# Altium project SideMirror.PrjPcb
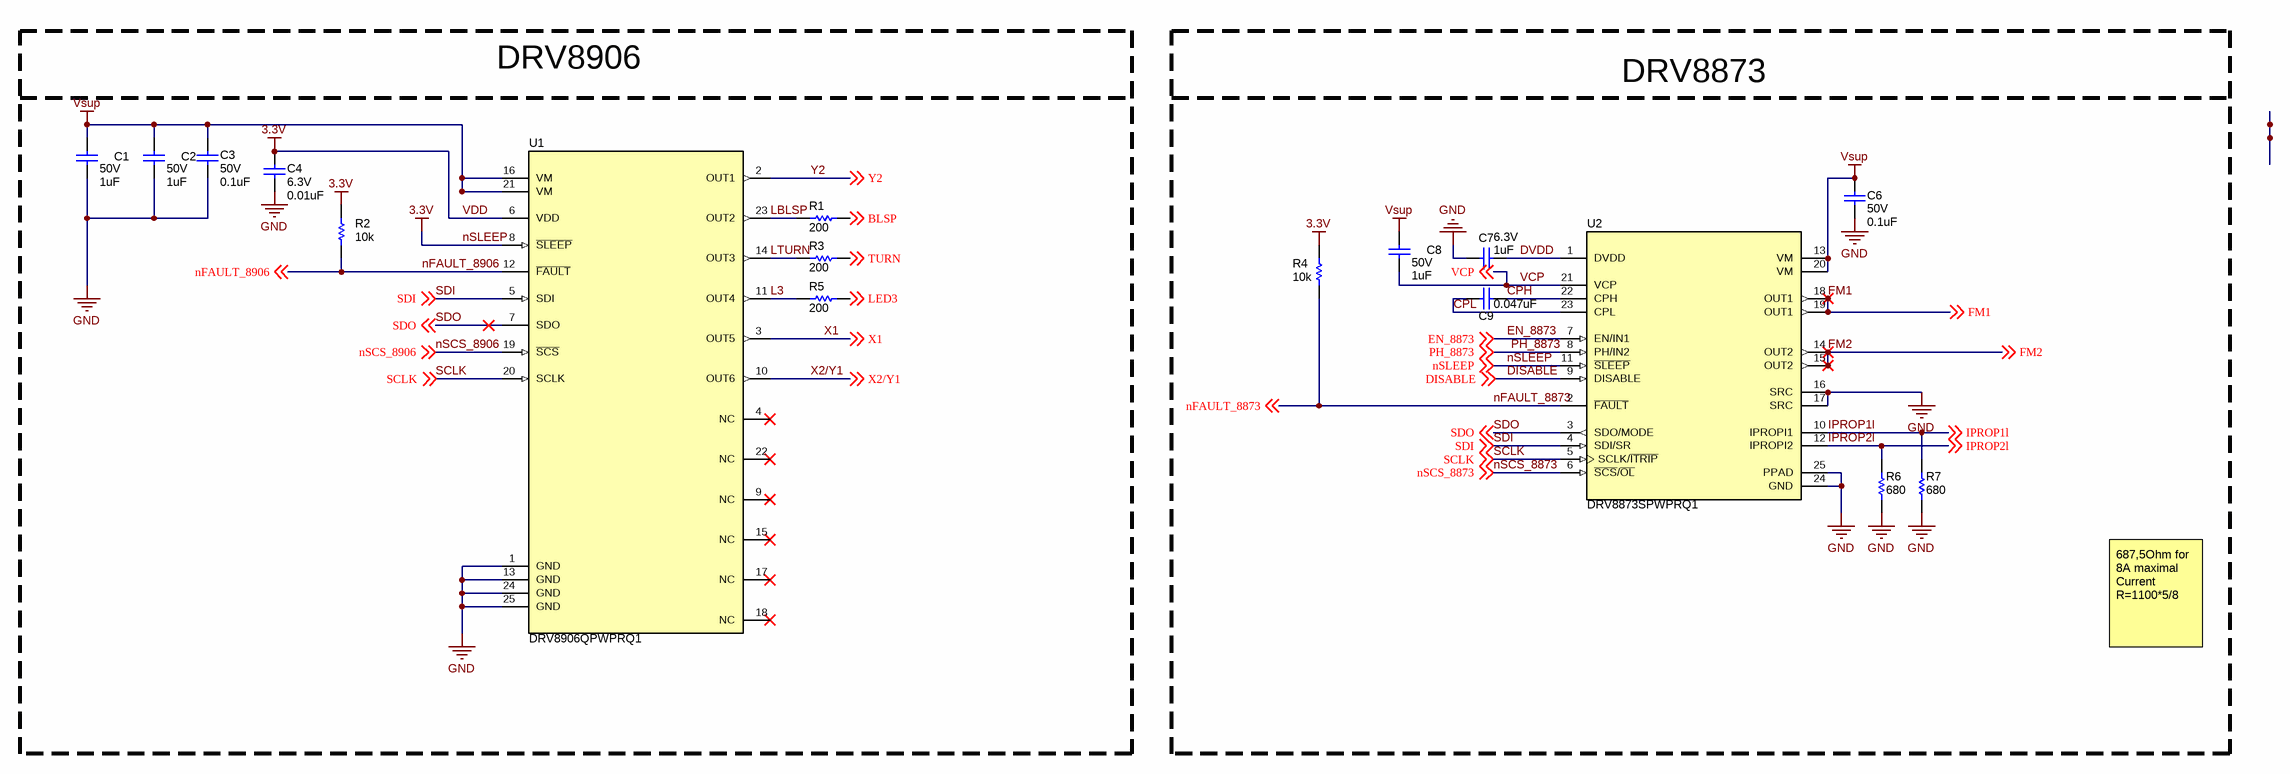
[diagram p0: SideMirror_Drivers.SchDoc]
TID: TIDA-020027; TechSupport: http://www.ti.com/support; SCH_Rev: E1; PRJ_Title: Side Mirror Module; PRJ_Number: TIDA-020027; PRJ_Engineer: Alisa Knorr; PRJ_Customer: Public Release; PCB_Rev: E1; PCB_Layout: Alisa Knorr; CopyrightYear: 2019
3 sheets, 78 parts. Net scope: global (net labels, ports and power ports of the same name join across sheets).
Board file: SideMirror_PCB.PcbDoc
Sheets:
  SideMirror_Drivers.SchDoc
  SideMirror_Logic_TLIN1028.SchDoc
  SideMirror_Hardware.SchDoc

## Sheet SideMirror_Drivers.SchDoc
size 431 x 279 mm; Date: Not shown in title block; ApprovedBy: Not shown in title block; CheckedBy: Not shown in title block; Author: Not shown in title block; CompanyName: Not shown in title block; Engineer: Not shown in title block; Organization: Not shown in title block; Address1: Not shown in title block; Address2: Not shown in title block; Address3: Not shown in title block; Address4: Not shown in title block; DocumentNumber: 2; Revision: Use project parameter SCH_Rev; SheetNumber: 1; SheetTotal: 3; PageSetup: Record=PageOptions¦CenterHorizontal=True¦CenterVertical=True¦PrintScale=1.00¦XCorrection=1.00¦YCorrection=1.00¦PrintKind=0¦BorderSize=5000000¦LeftOffset=0¦BottomOffset=0¦Orientation=2¦PaperLength=1000¦PaperWidth=1000¦Scale=100¦PaperSource=15¦PrintQuality=600¦MediaType=1¦DitherType=10¦PaperKind=Letter¦PrintScaleMode=1

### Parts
C1  VDC_V: 50V  ValueDisplayed: 1uF  [0603]  (hidden comment: UMK107AB7105KA-T)
C2  VDC_V: 50V  ValueDisplayed: 1uF  [0603]  (hidden comment: UMK107AB7105KA-T)
C3  VDC_V: 50V  ValueDisplayed: 0.1uF  [0603]  (hidden comment: C0603C104J5RACTU)
C4  VDC_V: 6.3V  ValueDisplayed: 0.01uF  [0603]  (hidden comment: GRM188R70J103KA01D)
C6  VDC_V: 50V  ValueDisplayed: 0.1uF  [0603]  (hidden comment: C0603C104J5RACTU)
C7  VDC_V: 6.3V  ValueDisplayed: 1uF  [0603]  (hidden comment: GRM185R60J105KE26D)
C8  VDC_V: 50V  ValueDisplayed: 1uF  [0603]  (hidden comment: UMK107AB7105KA-T)
C9  ValueDisplayed: 0.047uF  [0402L]  (hidden comment: Capacitor)
R1  ValueDisplayed: 200  [0603]  (hidden comment: CRCW0603200RJNEA)
R2  ValueDisplayed: 10k  [0402L]  (hidden comment: Resistor)
R3  ValueDisplayed: 200  [0603]  (hidden comment: CRCW0603200RJNEA)
R4  ValueDisplayed: 10k  [0402L]  (hidden comment: Resistor)
R5  ValueDisplayed: 200  [0603]  (hidden comment: CRCW0603200RJNEA)
R6  ValueDisplayed: 680  [0603]  (hidden comment: RC0603FR-07680RL)
R7  ValueDisplayed: 680  [0603]  (hidden comment: RC0603FR-07680RL)
U1  DRV8906QPWPRQ1  [PWP0024N_N]
U2  DRV8873SPWPRQ1  [PWP0024J_M]

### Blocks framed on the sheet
DRV8906: C1-C4 R1-R3 R5 U1
DRV8873: C6-C9 R4 R6 R7 U2

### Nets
3.3V: C4.1 R2.2 R4.2 U1.6(VDD) U1.8(~{SLEEP}) U2.11(~{SLEEP}) ; off-sheet nSLEEP  [also labelled nSLEEP, VDD]
GND: C1.2 C2.2 C3.1 C4.2 C6.1 C7.2 R6.1 R7.1 U1.1(GND) U1.13(GND) U1.24(GND) U1.25(GND) U2.16(SRC) U2.17(SRC) U2.24(GND) U2.25(PPAD)
Vsup: C1.1 C2.1 C3.2 C6.2 C8.1 U1.16(VM) U1.21(VM) U2.13(VM) U2.20(VM)
BLSP: R1.2 ; off-sheet BLSP
CPH: C9.1 U2.22(CPH)
CPL: C9.2 U2.23(CPL)
DISABLE: U2.9(DISABLE) ; off-sheet DISABLE
DVDD: C7.1 U2.1(DVDD)
EN_8873: U2.7(EN/IN1) ; off-sheet EN_8873
FM1: U2.18(OUT1) U2.19(OUT1) ; off-sheet FM1
FM2: U2.14(OUT2) U2.15(OUT2) ; off-sheet FM2
IPROP1l: R7.2 U2.10(IPROPI1) ; off-sheet IPROP1l
IPROP2l: R6.2 U2.12(IPROPI2) ; off-sheet IPROP2l
L3: R5.1 U1.11(OUT4)
LBLSP: R1.1 U1.23(OUT2)
LED3: R5.2 ; off-sheet LED3
LTURN: R3.1 U1.14(OUT3)
nFAULT_8873: R4.1 U2.2(~{FAULT}) ; off-sheet nFAULT_8873
nFAULT_8906: R2.1 U1.12(~{FAULT}) ; off-sheet nFAULT_8906
nSCS_8873: U2.6(~{SCS}/~{OL}) ; off-sheet nSCS_8873
nSCS_8906: U1.19(~{SCS}) ; off-sheet nSCS_8906
PH_8873: U2.8(PH/IN2) ; off-sheet PH_8873
SCLK: U1.20(SCLK) U2.5(SCLK/~{ITRIP}) ; off-sheet SCLK
SDI: U1.5(SDI) U2.4(SDI/SR) ; off-sheet SDI
SDO: U1.7(SDO) U2.3(SDO/MODE) ; off-sheet SDO
TURN: R3.2 ; off-sheet TURN
VCP: C8.2 U2.21(VCP) ; off-sheet VCP
X1: U1.3(OUT5) ; off-sheet X1
X2/Y1: U1.10(OUT6) ; off-sheet X2/Y1
Y2: U1.2(OUT1) ; off-sheet Y2

Not connected (* = marked no-connect by the designer): U1 4(NC)* 9(NC)* 15(NC)* 17(NC)* 18(NC)* 22(NC)*

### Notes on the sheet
- 687,5Ohm for 8A maximal Current
  R=1100*5/8
- Labels drawn without touching a wire or pin: EN_8873, PH_8873, SCLK

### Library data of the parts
C1 C2 C8 = CMP-0007508-5: CAP, CERM, 1 uF, 50 V, +/- 10%, X7R, 0603; Manufacturer: Taiyo Yuden; TaMin_C: -55°C; Polarized: N; SizeAreaWB_mm2: 4.68; Value1: Unknown; U/M: EA; Value: 1uF; TaMax_C: 125°C; SizeZ_mm: 1; SizeX_mm: 1.6; SizeY_mm: 0.8; SizeArea_mm2: 1.28; Cap_F: 1µF; AEC Category: Q200
C3 C6 = CMP-0006858-4: CAP, CERM, 0.1 uF, 50 V, +/- 5%, X7R, 0603; Manufacturer: Kemet; TaMin_C: -55°C; Polarized: N; SizeAreaWB_mm2: 4.68; Value1: Unknown; U/M: EA; Value: 0.1uF; TaMax_C: 125°C; SizeZ_mm: 1; SizeX_mm: 1.6; SizeY_mm: 0.8; SizeArea_mm2: 1.28; Cap_F: 100nF; AEC Category: Q200
C4 = CMP-0007358-5: CAP, CERM, 0.01 uF, 6.3 V, +/- 10%, X7R, 0603; Manufacturer: MuRata; TaMin_C: -55°C; Polarized: N; SizeAreaWB_mm2: 4.68; Value1: Unknown; U/M: EA; Value: 0.01uF; TaMax_C: 125°C; SizeZ_mm: 1; SizeX_mm: 1.6; SizeY_mm: 0.8; SizeArea_mm2: 1.28; Cap_F: 10nF; AEC Category: Q200
C7 = CMP-0007155-1: CAP, CERM, 1 uF, 6.3 V, +/- 10%, X5R, 0603; Manufacturer: MuRata; TaMin_C: -55°C; Polarized: N; SizeAreaWB_mm2: 4.68; Value1: Unknown; U/M: EA; Value: 1uF; TaMax_C: 85°C; SizeZ_mm: 1; SizeX_mm: 1.6; SizeY_mm: 0.8; SizeArea_mm2: 1.28; Cap_F: 1µF; AEC Category: Q200
C9 = CMP-0006280-2: CAP, CERM, 0.047 uF, 50 V, +/- 10%, X5R, 0402; PartNumber: C1005X5R1H473K050BB; Manufacturer: TDK; Polarized: N; U/M: EA; Cap_F: 47nF; ESR_ohm: 0.06407; Value1: 0.06407 ohm; VDC_V: 50V; IRMS_A: 6.46122dA; TaMin_C: -55°C; TaMax_C: 85°C; Cap_Case: 0402; SizeArea_mm2: 0.5; SizeAreaWB_mm2: 3; SizeX_mm: 1; SizeZ_mm: 0.6; AEC Category: Q200
R1 R3 R5 = CMP-0025752-4: RES, 200, 5%, 0.1 W, AEC-Q200 Grade 0, 0603; Manufacturer: Vishay-Dale; Power_W: 100mW; TempCo: 200 ppm/C; Value_Code: 200R; Value: 200; EIA_Code: E24; SizeX_mm: 1.6; SizeY_mm: 0.8; SizeZ_mm: 1; Value2: 0.1W; SizeArea_mm2: 1.28; AEC Qualified: Y; VDC_V: 75V; AEC Category: Q200; AEC Grade: 0
R2 R4 = CMP-0026825-5: RES, 10 k, 5%, 0.063 W, AEC-Q200 Grade 0, 0402; PartNumber: CRCW040210K0JNED; Manufacturer: Vishay-Dale; Value: 10k; Value_Code: 10k0; Power_W: 63mW; Value2: 0.063W; VDC_V: 50V; TempCo: 200 ppm/C; SizeArea_mm2: 0.5; SizeX_mm: 1; SizeZ_mm: 0.6; EIA_Code: E24; AEC Category: Q200; AEC Qualified: Y; AEC Grade: 0
R6 R7 = CMP-0023235-5: RES, 680, 1%, 0.1 W, 0603; Manufacturer: Yageo; Power_W: 100mW; TempCo: 100 ppm/C; Value_Code: 680R; Value: 680; SizeX_mm: 1.6; SizeY_mm: 0.8; SizeZ_mm: 1; Value2: 0.1W; SizeArea_mm2: 1.28; AEC Qualified: N; VDC_V: 75V; AEC Category: Q200; SizeAreaWB_mm2: 4.68
U1 = CMP-0860359-2: DRV8906QPWPRQ1, PWP0024N (HTSSOP-24); Alternate PartNumber: DRV8906QPWTRQ1; Manufacturer: Texas Instruments; AEC Category: Q200; SizeZ_mm: 1.2; AEC Qualified: Y; CompType: IC; SizeArea_mm2: 50.076; SizeY_mm: 7.8; SizeX_mm: 6.42; SizeAreaWB_mm2: 82.516
U2 = CMP-0065213-5: Automotive H-Bridge Motor Driver, PWP0024J (TSSOP-24); Manufacturer: Texas Instruments; SizeZ_mm: 1.2; SizeX_mm: 6.4; SizeY_mm: 7.8; SizeArea_mm2: 49.92; CompType: IC; SizeAreaWB_mm2: 82.32; AEC Category: Q200; AEC Qualified: Y

## Sheet SideMirror_Logic_TLIN1028.SchDoc
size 431 x 279 mm; Date: Not shown in title block; ApprovedBy: Not shown in title block; CheckedBy: Not shown in title block; Author: Not shown in title block; CompanyName: Not shown in title block; Engineer: Not shown in title block; Organization: Not shown in title block; Address1: Not shown in title block; Address2: Not shown in title block; Address3: Not shown in title block; Address4: Not shown in title block; DocumentNumber: 2; Revision: Use project parameter SCH_Rev; SheetNumber: 2; SheetTotal: 3; PageSetup: Record=PageOptions¦CenterHorizontal=True¦CenterVertical=True¦PrintScale=1.00¦XCorrection=1.00¦YCorrection=1.00¦PrintKind=0¦BorderSize=5000000¦LeftOffset=0¦BottomOffset=0¦Orientation=2¦PaperLength=1000¦PaperWidth=1000¦Scale=100¦PaperSource=15¦PrintQuality=600¦MediaType=1¦DitherType=10¦PaperKind=Letter¦PrintScaleMode=1
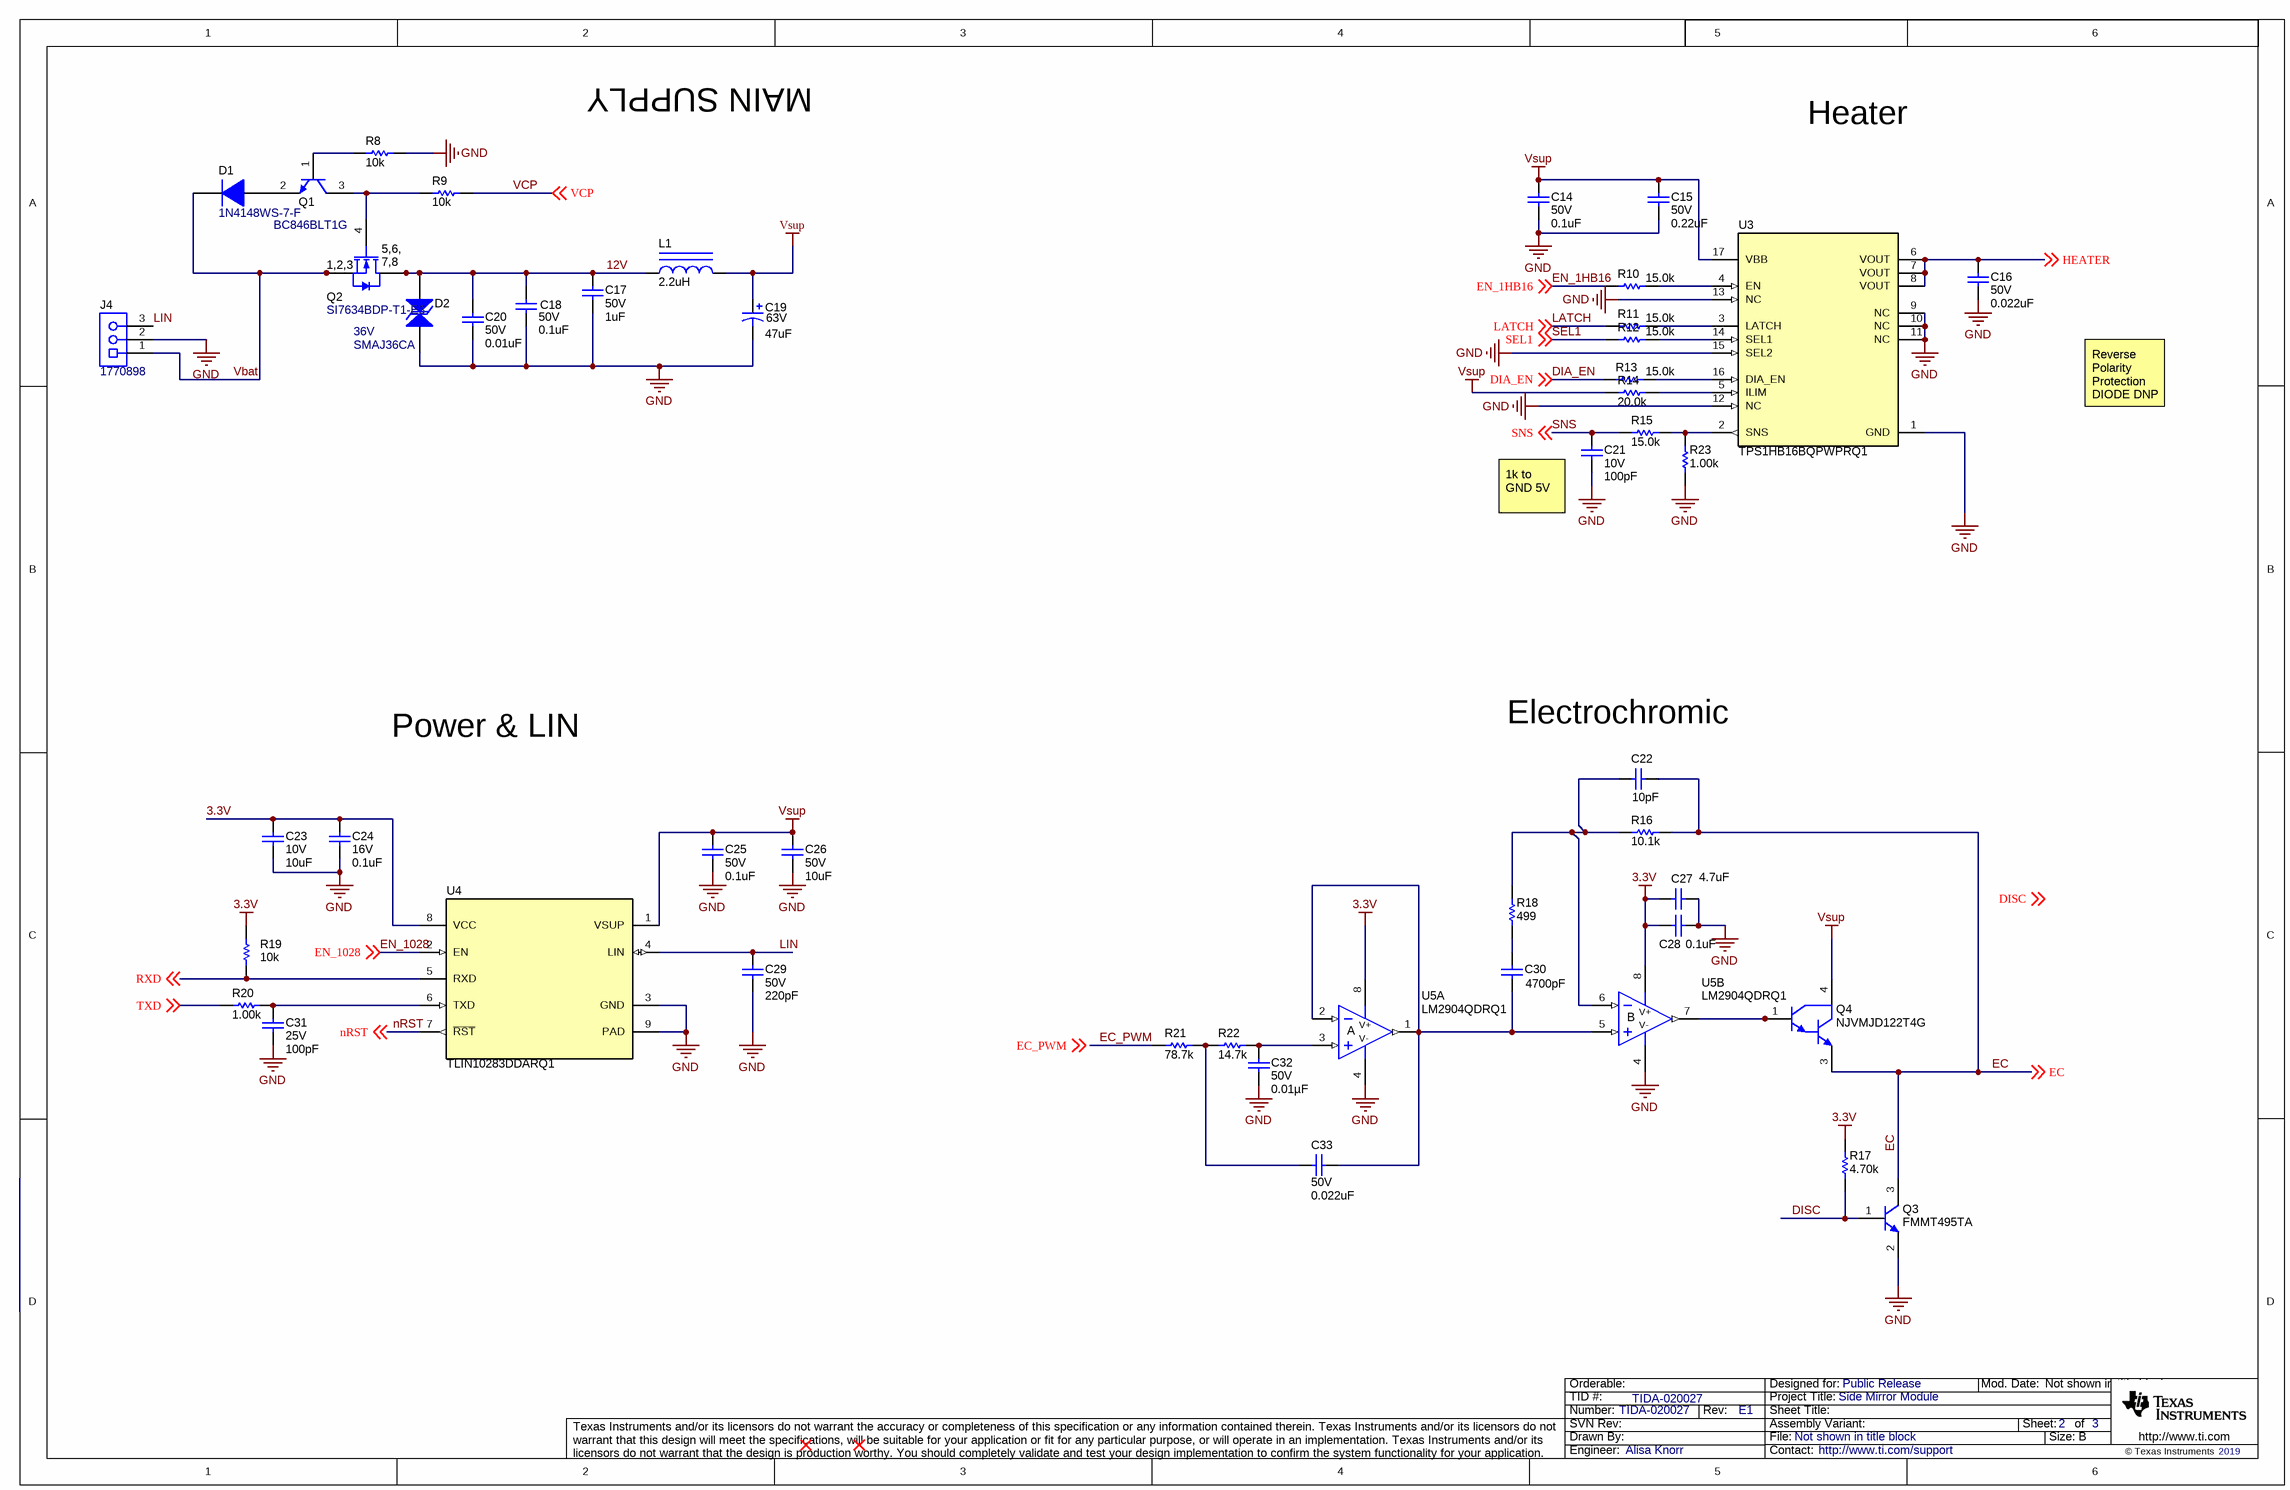
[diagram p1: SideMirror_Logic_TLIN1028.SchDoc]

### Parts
C14  VDC_V: 50V  ValueDisplayed: 0.1uF  [0603]  (hidden comment: GRM188R71H104KA93D)
C15  VDC_V: 50V  ValueDisplayed: 0.22uF  [0603]  (hidden comment: GRM188R71H224KAC4D)
C16  VDC_V: 50V  ValueDisplayed: 0.022uF  [0603]  (hidden comment: C0603X223K5RACTU)
C17  VDC_V: 50V  ValueDisplayed: 1uF  [0805_HV]  (hidden comment: GRM21BR71H105KA12L)
C18  VDC_V: 50V  ValueDisplayed: 0.1uF  [0603]  (hidden comment: C1608X7R1H104K080AA)
C19  VDC_V: 63V  ValueDisplayed: 47uF  [SM_RADIAL_F]  (hidden comment: EEE-FK1J470P)
C20  VDC_V: 50V  ValueDisplayed: 0.01uF  [0603]  (hidden comment: C1608X7R1H103K080AA)
C21  VDC_V: 10V  ValueDisplayed: 100pF  [0603]  (hidden comment: 0603ZC101KAT2A)
C22  ValueDisplayed: 10pF  [0603]  (hidden comment: 0603ZC100KAT2A)
C23  VDC_V: 10V  ValueDisplayed: 10uF  [0603]  (hidden comment: GRM188Z71A106MA73D)
C24  VDC_V: 16V  ValueDisplayed: 0.1uF  [0603]  (hidden comment: C0603C104K4RACTU)
C25  VDC_V: 50V  ValueDisplayed: 0.1uF  [0603]  (hidden comment: C1608X7R1H104K080AA)
C26  VDC_V: 50V  ValueDisplayed: 10uF  [1206]  (hidden comment: CGA5L3X5R1H106M160AB)
C27  ValueDisplayed: 4.7uF  [0603]  (hidden comment: GRM188Z71C475KE21D)
C28  ValueDisplayed: 0.1uF  [0603]  (hidden comment: GCM188R71C104KA37J)
C29  VDC_V: 50V  ValueDisplayed: 220pF  [0603]  (hidden comment: C0603C221K5RACTU)
C30  ValueDisplayed: 4700pF  [0603]  (hidden comment: GCM188R71H472KA37D)
C31  VDC_V: 25V  ValueDisplayed: 100pF  [0603]  (hidden comment: 06033C101KAT2A)
C32  VDC_V: 50V  ValueDisplayed: 0.01µF  [0402]  (hidden comment: CGA2B3X8R1H103K050BB)
C33  VDC_V: 50V  ValueDisplayed: 0.022uF  [0402]  (hidden comment: GRM155R71H223KA12D)
D1  1N4148WS-7-F  [SOD-323]
D2  SMAJ36CA  value 36V  [SMA_Bi]
J4  1770898  [Phoenix_1770898]
L1  ValueDisplayed: 2.2uH  [SRP6540]  (hidden comment: SRP6540-2R2M)
Q1  BC846BLT1G  [SOT-23]
Q2  SI7634BDP-T1-E3  [PowerPAK_SO-8]
Q3  FMMT495TA  [SOT-23]
Q4  NJVMJD122T4G  [DPAK]
R8  ValueDisplayed: 10k  [0402]  (hidden comment: CRCW040210K0JNED)
R9  ValueDisplayed: 10k  [0402]  (hidden comment: CRCW040210K0JNED)
R10  ValueDisplayed: 15.0k  [0603]  (hidden comment: CRCW060315K0FKEA)
R11  ValueDisplayed: 15.0k  [0603]  (hidden comment: CRCW060315K0FKEA)
R12  ValueDisplayed: 15.0k  [0603]  (hidden comment: CRCW060315K0FKEA)
R13  ValueDisplayed: 15.0k  [0603]  (hidden comment: CRCW060315K0FKEA)
R14  ValueDisplayed: 20.0k  [0603]  (hidden comment: CRCW060320K0FKEA)
R15  ValueDisplayed: 15.0k  [0603]  (hidden comment: CRCW060315K0FKEA)
R16  ValueDisplayed: 10.1k  [0603]  (hidden comment: RT0603DRE0710K1L)
R17  ValueDisplayed: 4.70k  [0603]  (hidden comment: RC0603FR-074K7L)
R18  ValueDisplayed: 499  [0603]  (hidden comment: CRCW0603499RFKEA)
R19  ValueDisplayed: 10k  [0402L]  (hidden comment: Resistor)
R20  ValueDisplayed: 1.00k  [0603]  (hidden comment: CRCW06031K00FKEA)
R21  ValueDisplayed: 78.7k  [0603]  (hidden comment: CRCW060378K7FKEA)
R22  ValueDisplayed: 14.7k  [0603]  (hidden comment: CRCW060314K7FKEA)
R23  ValueDisplayed: 1.00k  [0603]  (hidden comment: ERJ-3EKF1001V)
U3  PartNumber: TPS1HB16BQPWPRQ1  [PWP0016M_N]  (hidden comment: TPS1HB16BQPWPTQ1)
U4  PartNumber: TLIN10283DDARQ1  [DDA0008G_L]  (hidden comment: TLIN1028DDA)
U5  LM2904QDRQ1  [D0008A_L]  (parts A,B of 2)

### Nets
3.3V: C23.2 C24.2 C27.1 C28.1 R17.2 R19.2 U4.8(VCC) U5.8(V+)
GND: C14.2 C15.2 C16.2 C17.2 C18.2 C19.2(-) C20.2 C21.1 C23.1 C24.1 C25.1 C26.2 C27.2 C28.2 C29.2 C31.1 C32.2 D2.2 J4.2 Q3.2(E) R8.2 R23.1 U3.1(GND) U3.9(NC) U3.10(NC) U3.11(NC) U3.12(NC) U3.13(NC) U3.15(SEL2) U4.3(GND) U4.9(PAD) U5.4(V-)
Vsup: C14.1 C15.1 C19.1(+) C25.2 C26.1 L1.2 Q4.4(C) R14.1 U3.17(VBB) U4.1(VSUP)
12V: C17.1 C18.1 C20.1 D2.1 L1.1 Q2.5(D) Q2.6(D) Q2.7(D) Q2.8(D) Q2.9(D)
DIA_EN: R13.1 ; off-sheet DIA_EN
DISC: Q3.1(B) R17.1 ; off-sheet DISC
EC: C22.1 Q3.3(C) Q4.3(E) R16.2 ; off-sheet EC
EC_PWM: R21.1 ; off-sheet EC_PWM
EN_1HB16: R10.1 ; off-sheet EN_1HB16
EN_1028: U4.2(EN) ; off-sheet EN_1028
HEATER: C16.1 U3.6(VOUT) U3.7(VOUT) U3.8(VOUT) ; off-sheet HEATER
LATCH: R11.1 ; off-sheet LATCH
LIN: C29.1 J4.3 U4.4(LIN)
nRST: U4.7(~{RST}) ; off-sheet nRST
RXD: R19.1 U4.5(RXD) ; off-sheet RXD
SEL1: R12.1 ; off-sheet SEL1
SNS: C21.2 R15.1 ; off-sheet SNS
TXD: R20.1 ; off-sheet TXD
Vbat: D1.1(K) J4.1 Q2.1(S) Q2.2(S) Q2.3(S)
VCP: R9.2 ; off-sheet VCP
NetC22_2: C22.2 R16.1 R18.2 U5.6(IN-)
NetC30_1: C30.1 R18.1
NetC30_2: C30.2 C33.1 U5.1(OUT) U5.2(IN-) U5.5(IN+)
NetC31_2: C31.2 R20.2 U4.6(TXD)
NetC32_1: C32.1 R22.2 U5.3(IN+)
NetC33_2: C33.2 R21.2 R22.1
NetD1_2: D1.2(A) Q1.2(E)
NetQ1_1: Q1.1(B) R8.1
NetQ1_3: Q1.3(C) Q2.4(G) R9.1
NetQ4_1: Q4.1(B) U5.7(OUT)
NetR10_2: R10.2 U3.4(EN)
NetR11_2: R11.2 U3.3(LATCH)
NetR12_2: R12.2 U3.14(SEL1)
NetR13_2: R13.2 U3.16(DIA_EN)
NetR14_2: R14.2 U3.5(ILIM)
NetR15_2: R15.2 R23.2 U3.2(SNS)

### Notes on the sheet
- MAIN SUPPLY
- Heater
- Reverse Polarity Protection
  DIODE DNP
- (near C21) 1k to GND 5V
- (near C22) Electrochromic
- Power & LIN
- Labels drawn without touching a wire or pin: DISC, EC_PWM

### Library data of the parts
C14 = CMP-0007434-4: CAP, CERM, 0.1 uF, 50 V, +/- 10%, X7R, 0603; Manufacturer: MuRata; TaMin_C: -55°C; Polarized: N; SizeAreaWB_mm2: 4.68; Value1: Unknown; U/M: EA; Value: 0.1uF; TaMax_C: 125°C; SizeZ_mm: 1; SizeX_mm: 1.6; SizeY_mm: 0.8; SizeArea_mm2: 1.28; Cap_F: 100nF; AEC Category: Q200
C15 = CMP-0007445-4: CAP, CERM, 0.22 uF, 50 V, +/- 10%, X7R, 0603; Manufacturer: MuRata; TaMin_C: -55°C; Polarized: N; SizeAreaWB_mm2: 4.68; Value1: Unknown; U/M: EA; Value: 0.22uF; TaMax_C: 125°C; SizeZ_mm: 1; SizeX_mm: 1.6; SizeY_mm: 0.8; SizeArea_mm2: 1.28; Cap_F: 220nF; AEC Category: Q200
C16 = CMP-0006984-4: CAP, CERM, 0.022 uF, 50 V, +/- 10%, X7R, 0603; Manufacturer: Kemet; TaMin_C: -55°C; Polarized: N; SizeAreaWB_mm2: 4.68; Value1: Unknown; U/M: EA; TaMax_C: 125°C; SizeZ_mm: 1; SizeX_mm: 1.6; SizeY_mm: 0.8; SizeArea_mm2: 1.28; Cap_F: 22nF; AEC Category: Q200
C17 = CMP-0008350-2: CAP, CERM, 1 uF, 50 V, +/- 10%, X7R, 0805; Manufacturer: MuRata; TaMin_C: -55°C; Polarized: N; SizeAreaWB_mm2: 6.75; Value1: Unknown; U/M: EA; Value: 1uF; TaMax_C: 125°C; SizeZ_mm: 1.45; SizeX_mm: 2; SizeY_mm: 1.25; Cap_Case: 0805; SizeArea_mm2: 2.5; Cap_F: 1µF; AEC Category: Q200
C18 C25 = CMP-0007044-5: CAP, CERM, 0.1 uF, 50 V, +/- 10%, X7R, 0603; Manufacturer: TDK; TaMin_C: -55°C; ESR_ohm: 0.0296; Polarized: N; SizeAreaWB_mm2: 4.68; Value1: 0.0296 ohm; U/M: EA; Value: 0.1uF; TaMax_C: 125°C; SizeZ_mm: 1; SizeX_mm: 1.6; SizeY_mm: 0.8; SizeArea_mm2: 1.28; Cap_F: 100nF; IRMS_A: 971.99mA; AEC Category: Q200
C19 = CMP-0011192-2: CAP, AL, 47 uF, 63 V, +/- 20%, 0.65 ohm, AEC-Q200 Grade 2, SMD; Manufacturer: Panasonic; TaMin_C: -55°C; ESR_ohm: 0.65; Polarized: Y; SizeAreaWB_mm2: 123.6; U/M: EA; Value: 47uF; TaMax_C: 105°C; SizeZ_mm: 10.2; SizeX_mm: 10; SizeY_mm: 8.3; Cap_Case: F; SizeArea_mm2: 83; CompType: Capacitor; Cap_F: 47µF; IRMS_A: 250mA; AEC Grade: 2; AEC Category: Q200
C20 = CMP-0007043-4: CAP, CERM, 0.01 uF, 50 V, +/- 10%, X7R, 0603; Manufacturer: TDK; TaMin_C: -55°C; ESR_ohm: 0.0539; Polarized: N; SizeAreaWB_mm2: 4.68; Value1: 0.0539 ohm; U/M: EA; Value: 0.01uF; TaMax_C: 125°C; SizeZ_mm: 1; SizeX_mm: 1.6; SizeY_mm: 0.8; SizeArea_mm2: 1.28; Cap_F: 10nF; AEC Category: Q200
C21 = CMP-0006812-4: CAP, CERM, 100 pF, 10 V, +/- 10%, X7R, 0603; Manufacturer: AVX; TaMin_C: -55°C; Polarized: N; SizeAreaWB_mm2: 4.68; Value1: Unknown; U/M: EA; Value: 100pF; TaMax_C: 125°C; SizeZ_mm: 1; SizeX_mm: 1.6; SizeY_mm: 0.8; SizeArea_mm2: 1.28; AEC Category: Q200
C22 = CMP-0006811-2: CAP, CERM, 10 pF, 10 V, +/- 10%, X7R, 0603; Manufacturer: AVX; TaMin_C: -55°C; Polarized: N; SizeAreaWB_mm2: 4.68; Value1: Unknown; U/M: EA; Value: 10pF; TaMax_C: 125°C; SizeZ_mm: 1; SizeX_mm: 1.6; SizeY_mm: 0.8; Value2: 10V; SizeArea_mm2: 1.28; AEC Category: Q200
C23 = CMP-0007497-5: CAP, CERM, 10 uF, 10 V, +/- 20%, X7R, 0603; Manufacturer: MuRata; TaMin_C: -55°C; Polarized: N; SizeAreaWB_mm2: 4.68; Value1: Unknown; U/M: EA; Value: 10uF; TaMax_C: 125°C; SizeZ_mm: 1; SizeX_mm: 1.6; SizeY_mm: 0.8; SizeArea_mm2: 1.28; Cap_F: 10µF; AEC Category: Q200
C24 = CMP-0006860-5: CAP, CERM, 0.1 uF, 16 V, +/- 10%, X7R, 0603; Manufacturer: Kemet; TaMin_C: -55°C; Polarized: N; SizeAreaWB_mm2: 4.68; Value1: Unknown; U/M: EA; Value: 0.1uF; TaMax_C: 125°C; SizeZ_mm: 1; SizeX_mm: 1.6; SizeY_mm: 0.8; SizeArea_mm2: 1.28; Cap_F: 100nF; AEC Category: Q200
C26 = CMP-0008785-1: CAP, CERM, 10 uF, 50 V, +/- 20%, X5R, AEC-Q200 Grade 3, 1206; Manufacturer: TDK; TaMin_C: -55°C; Polarized: N; SizeAreaWB_mm2: 10.92; Value1: Unknown; U/M: EA; Value: 10uF; TaMax_C: 85°C; SizeZ_mm: 1.35; SizeX_mm: 3.2; SizeY_mm: 1.6; SizeArea_mm2: 5.12; AEC Qualified: Y; Cap_F: 10µF; AEC Grade: 3; AEC Category: Q200
C27 = CMP-0064936-2: CAP, CERM, 4.7 uF, 16 V,+/- 10%, X7R, 0603; Manufacturer: MuRata; TaMin_C: -55°C; Polarized: N; SizeAreaWB_mm2: 4.68; Value1: Unknown; U/M: EA; Value: 4.7uF; TaMax_C: 125°C; SizeZ_mm: 1; SizeX_mm: 1.6; SizeY_mm: 0.8; Value2: 16V; SizeArea_mm2: 1.28; Cap_F: 4.7µF; AEC Category: Q200
C28 = CMP-0007135-2: CAP, CERM, 0.1 uF, 16 V, +/- 10%, X7R, AEC-Q200 Grade 1, 0603; Manufacturer: MuRata; TaMin_C: -55°C; Polarized: N; SizeAreaWB_mm2: 4.68; Value1: Unknown; U/M: EA; Value: 0.1uF; TaMax_C: 125°C; SizeZ_mm: 1; SizeX_mm: 1.6; SizeY_mm: 0.8; Value2: 16V; SizeArea_mm2: 1.28; AEC Qualified: Y; Cap_F: 100nF; AEC Category: Q200
C29 = CMP-0006895-4: CAP, CERM, 220 pF, 50 V, +/- 10%, X7R, 0603; Manufacturer: Kemet; TaMin_C: -55°C; Polarized: N; SizeAreaWB_mm2: 4.68; Value1: Unknown; U/M: EA; Value: 220pF; TaMax_C: 125°C; SizeZ_mm: 1; SizeX_mm: 1.6; SizeY_mm: 0.8; SizeArea_mm2: 1.28; AEC Category: Q200
C30 = CMP-0007146-2: CAP, CERM, 4700 pF, 50 V, +/- 10%, X7R, AEC-Q200 Grade 1, 0603; Manufacturer: MuRata; TaMin_C: -55°C; Polarized: N; SizeAreaWB_mm2: 4.68; Value1: Unknown; U/M: EA; Value: 4700pF; TaMax_C: 125°C; SizeZ_mm: 1; SizeX_mm: 1.6; SizeY_mm: 0.8; Value2: 50V; SizeArea_mm2: 1.28; AEC Qualified: Y; Cap_F: 4.7nF; AEC Category: Q200
C31 = CMP-0006751-4: CAP, CERM, 100 pF, 25 V, +/- 10%, X7R, 0603; Manufacturer: AVX; TaMin_C: -55°C; Polarized: N; SizeAreaWB_mm2: 4.68; Value1: Unknown; U/M: EA; Value: 100pF; TaMax_C: 125°C; SizeZ_mm: 1; SizeX_mm: 1.6; SizeY_mm: 0.8; SizeArea_mm2: 1.28; AEC Category: Q200
C32 = CMP-0078224-1: CAP, CERM, 0.01 µF, 50 V,+/- 10%, X8R, AEC-Q200 Grade 0, 0402; Manufacturer: TDK; TaMin_C: -55°C; Polarized: N; SizeAreaWB_mm2: 3; U/M: EA; Value: 0.01uF; TaMax_C: 150°C; SizeZ_mm: 0.6; SizeX_mm: 1; SizeY_mm: 0.5; CompType: Capacitor; AEC Qualified: Y; Cap_F: 10nF; AEC Grade: 0; AEC Category: Q200
C33 = CMP-0006684-1: CAP, CERM, 0.022 uF, 50 V, +/- 10%, X7R, 0402; Manufacturer: MuRata; TaMin_C: -55°C; Polarized: N; SizeAreaWB_mm2: 3; Value1: Unknown; U/M: EA; TaMax_C: 125°C; SizeZ_mm: 0.6; SizeX_mm: 1; SizeY_mm: 0.5; Cap_F: 22nF; AEC Category: Q200
D1 = CMP-0079597-1: Diode, Switching, 75 V, 0.15 A, AEC-Q101, SOD-323; Manufacturer: Diodes Inc.; SizeAreaWB_mm2: 8.695; Vr_V: 75V; SizeArea_mm2: 3.645; AEC Qualified: Y; TJmax_C: 150°C; AEC Category: Q101; Value: 75V; SizeZ_mm: 1; Io_A: 150mA; Vf_V: 1.25V; SizeY_mm: 1.35; Value1: 0.15A; SizeX_mm: 2.7
D2 = CMP-0085017-1: Diode, TVS, Bi, 36 V, 58.1 Vc, 400 W, 6.9 A, SMA (non-polarized); Manufacturer: Littelfuse; RJA_CperW: 120; SizeAreaWB_mm2: 32.368125; Vbr_Min: 40V; AEC Qualified: N; SizeArea_mm2: 13.068125; Vc: 58.1V; SizeZ_mm: 2.65; Ipp: 6.9A; AEC Category: Q101; SizeY_mm: 2.575; SizeX_mm: 5.075; Ppk: 400W; Vbr_Max: 44.2V
J4 = CMP-0084507-1: Terminal Block, 3 Pos, 2.5mm, R/A, TH; Manufacturer: Phoenix Contact; Gender: Female; Cert_VDE: Y; Pitch_mm: 2.5; Voltage_V: 160V; Row_Count: 1; Current_A: 6A
L1 = CMP-0056962-1: Inductor, Shielded, Ferrite, 2.2 uH, 9 A, 0.0155 ohm, SMD; Manufacturer: Bourns; Isat: 9A @ 20% inductance drop; Irms: 9A @ 40C rise; Green_Lifecycle: Active; SizeAreaWB_mm2: 82.65; DCR_ohm: 0.0155; Green_REACh: Passed; Value: 2.2uH; Imax_A: 9A; SizeX_mm: 7.5; SizeY_mm: 6.7; SizeArea_mm2: 50.25; SizeZ_mm: 4; Ind_H: 2.2µH; AEC Category: Q200
Q1 = CMP-0000375-2: Transistor, NPN, 65 V, 0.1 A, SOT-23; Manufacturer: ON Semiconductor; TaMax_C: 150°C; Value2: 450; Value1: 0.1 A; Vcesat1_V: 700mV; SizeX_mm: 2.5; SizeY_mm: 3; TaMin_C: -55°C; IcRated_A: 100mA; CompType: BJT; SizeZ_mm: 1.1; Value: 65 V; SizeArea_mm2: 7.5; NPN: 1; Vceo_V: 65V; PNP: 0; AEC Category: Q101; SizeAreaWB_mm2: 14; U/M: EA
Q2 = CMP-0082509-1: MOSFET, N-CH, 30 V, 40 A, PowerPAK SO-8; Manufacturer: Vishay-Siliconix; Alternate Manufacturer: None; ChType: N; QgTyp_nC: 45.5; SizeAreaWB_mm2: 55.131; SizeArea_mm2: 29.351; IdsMax_A: 40A; VdsMax_V: 30V; Rdson45_ohm: 7m; Vgs_V: 20V; AEC Category: Q101; Value: 30V; SizeZ_mm: 1.12; ChMode: Enhancement; SizeY_mm: 4.9; Value2: 45.5 nC; Value1: 0.007 ohm; SizeX_mm: 5.99
Q3 = CMP-0074710-1: Transistor, NPN, 150 V, 1 A, AEC-Q101, SOT-23; Manufacturer: Diodes Inc.; TaMin_C: -55°C; HfeMax: 300.0; SizeAreaWB_mm2: 14.0; Value1: 1 A; Vceo_V: 150V; U/M: EA; Value: 150 V; TaMax_C: 150°C; IcRated_A: 1A; SizeZ_mm: 1.1; SizeX_mm: 2.5; SizeY_mm: 3.0; SizeArea_mm2: 7.5; CompType: BJT; PNP: 0.0; AEC Qualified: Y; NPN: 1.0; Vcesat1_V: 3dV; AEC Category: Q101
Q4 = CMP-0077549-1: Transistor, NPN, 100 V, 8 A, AEC-Q101, DPAK; Manufacturer: ON Semiconductor; SizeAreaWB_mm2: 101.7114; NPN: 1; SizeArea_mm2: 64.8114; AEC Qualified: Y; IcRated_A: 8A; AEC Category: Q101; Value: 100 V; TaMax_C: 150°C; SizeZ_mm: 2.29; PNP: 0; Vceo_V: 100V; TaMin_C: -65°C; SizeY_mm: 6.54; U/M: EA; Value1: 8 A; CompType: BJT; Vcesat1_V: 2V; SizeX_mm: 9.91
R8 R9 = CMP-0026825-4: RES, 10 k, 5%, 0.063 W, 0402; Manufacturer: Vishay-Dale; Power_W: 63mW; TempCo: 200 ppm/C; Value_Code: 10k0; U/M: EA; Value: 10k; EIA_Code: E24; SizeX_mm: 1; SizeY_mm: 0.5; SizeZ_mm: 0.6; Value2: 0.063W; VDC_V: 50V; AEC Category: Q200
R10-R13 R15 = CMP-0022066-4: RES, 15.0 k, 1%, 0.1 W, AEC-Q200 Grade 0, 0603; Manufacturer: Vishay-Dale; Power_W: 100mW; TempCo: 100 ppm/C; Value_Code: 15k0; Value: 15.0k; EIA_Code: E96; Res_ohm: 15k; SizeX_mm: 1.6; SizeY_mm: 0.8; SizeZ_mm: 1; Value2: 0.1W; SizeArea_mm2: 1.28; AEC Qualified: Y; VDC_V: 75V; AEC Category: Q200; AEC Grade: 0
R14 = CMP-0022204-4: RES, 20.0 k, 1%, 0.1 W, AEC-Q200 Grade 0, 0603; Manufacturer: Vishay-Dale; Power_W: 100mW; TempCo: 100 ppm/C; Value_Code: 20k0; Value: 20.0k; EIA_Code: E96; Res_ohm: 20k; SizeX_mm: 1.6; SizeY_mm: 0.8; SizeZ_mm: 1; Value2: 0.1W; SizeArea_mm2: 1.28; AEC Qualified: Y; VDC_V: 75V; AEC Category: Q200; AEC Grade: 0
R16 = CMP-0024579-1: RES, 10.1 k, 0.5%, 0.1 W, 0603; Manufacturer: Yageo America; Power_W: 100mW; TempCo: 50 ppm/C; Value_Code: 10k1; U/M: EA; Value: 10.1k; EIA_Code: E192; SizeX_mm: 1.6; SizeY_mm: 0.8; SizeZ_mm: 1; Value2: 0.1W; SizeArea_mm2: 1.28; VDC_V: 75V; AEC Category: Q200
R17 = CMP-0023153-2: RES, 4.70 k, 1%, 0.1 W, 0603; Manufacturer: Yageo America; Power_W: 100mW; TempCo: 200 ppm/C; Value_Code: 4k70; U/M: EA; Value: 4.70k; Res_ohm: 4.7k; SizeX_mm: 1.6; SizeY_mm: 0.8; SizeZ_mm: 1; Value2: 0.1W; SizeArea_mm2: 1.28; VDC_V: 150V; AEC Category: Q200
R18 = CMP-0022446-3: RES, 499, 1%, 0.1 W, 0603; Manufacturer: Vishay-Dale; Power_W: 100mW; TempCo: 100 ppm/C; Value_Code: 499R; U/M: EA; Value: 499; EIA_Code: E96; SizeX_mm: 1.6; SizeY_mm: 0.8; SizeZ_mm: 1; Value2: 0.1W; SizeArea_mm2: 1.28; VDC_V: 75V; AEC Category: Q200
R19 = CMP-0026825-5: as R2 on sheet SideMirror_Drivers
R20 = CMP-0022109-5: RES, 1.00 k, 1%, 0.1 W, AEC-Q200 Grade 0, 0603; Manufacturer: Vishay-Dale; Power_W: 100mW; TempCo: 100 ppm/C; Value_Code: 1k00; Value: 1.00k; EIA_Code: E96; Res_ohm: 1k; SizeX_mm: 1.6; SizeY_mm: 0.8; SizeZ_mm: 1; Value2: 0.1W; SizeArea_mm2: 1.28; AEC Qualified: Y; VDC_V: 75V; AEC Category: Q200; AEC Grade: 0
R21 = CMP-0022597-4: RES, 78.7 k, 1%, 0.1 W, AEC-Q200 Grade 0, 0603; Manufacturer: Vishay-Dale; Power_W: 100mW; TempCo: 100 ppm/C; Value_Code: 78k7; Value: 78.7k; EIA_Code: E96; SizeX_mm: 1.6; SizeY_mm: 0.8; SizeZ_mm: 1; Value2: 0.1W; SizeArea_mm2: 1.28; AEC Qualified: Y; VDC_V: 75V; AEC Category: Q200; AEC Grade: 0
R22 = CMP-0022056-4: RES, 14.7 k, 1%, 0.1 W, AEC-Q200 Grade 0, 0603; Manufacturer: Vishay-Dale; Power_W: 100mW; TempCo: 100 ppm/C; Value_Code: 14k7; Value: 14.7k; EIA_Code: E96; SizeX_mm: 1.6; SizeY_mm: 0.8; SizeZ_mm: 1; Value2: 0.1W; SizeArea_mm2: 1.28; AEC Qualified: Y; VDC_V: 75V; AEC Category: Q200; AEC Grade: 0
R23 = CMP-0022680-4: RES, 1.00 k, 1%, 0.1 W, 0603; Manufacturer: Panasonic; Power_W: 100mW; TempCo: 100 ppm/C; Value_Code: 1k00; U/M: EA; Value: 1.00k; EIA_Code: E96; Res_ohm: 1k; SizeX_mm: 1.6; SizeY_mm: 0.8; SizeZ_mm: 1; SizeArea_mm2: 1.28; VDC_V: 75V; AEC Category: Q200; Value2: 0.1W
U3 = CMP-0080493-1: TPS1HB16BQPWPTQ1, PWP0016M (TSSOP-16); Alternate Manufacturer: Texas Instruments; SizeAreaWB_mm2: 58.8; SizeZ_mm: 1.2; SizeX_mm: 6.4; SizeY_mm: 5; SizeArea_mm2: 32; CompType: IC; AEC Qualified: Y; AEC Category: Q200
U4 = CMP-0074642-4: Automotive Local Interconnect Network Transceiver, DDA0008G (SOIC-8); Manufacturer: Texas Instruments; SizeZ_mm: 1.7; SizeX_mm: 5.99; SizeY_mm: 4.89; SizeArea_mm2: 29.2911; CompType: IC; U/M: EA; SizeAreaWB_mm2: 55.0511; AEC Category: Q200; AEC Qualified: N
U5 = CMP-0075745-1: Automotive Catalog Dual Operational Amplifier, D0008A (SOIC-8); Manufacturer: Texas Instruments; SizeAreaWB_mm2: 56.58; SizeArea_mm2: 30.38; SizeZ_mm: 1.75; SizeY_mm: 6.2; U/M: EA; CompType: IC; SizeX_mm: 4.9

## Sheet SideMirror_Hardware.SchDoc
size 431 x 279 mm; Date: Not shown in title block; ApprovedBy: Not shown in title block; CheckedBy: Not shown in title block; Author: Not shown in title block; CompanyName: Not shown in title block; Engineer: Not shown in title block; Organization: Not shown in title block; Address1: Not shown in title block; Address2: Not shown in title block; Address3: Not shown in title block; Address4: Not shown in title block; DocumentNumber: 3; Revision: Use project parameter SCH_Rev; SheetNumber: 3; SheetTotal: 3; PageSetup: Record=PageOptions¦CenterHorizontal=True¦CenterVertical=True¦PrintScale=1.00¦XCorrection=1.00¦YCorrection=1.00¦PrintKind=0¦BorderSize=5000000¦LeftOffset=0¦BottomOffset=0¦Orientation=2¦PaperLength=1000¦PaperWidth=1000¦Scale=100¦PaperSource=15¦PrintQuality=600¦MediaType=1¦DitherType=10¦PaperKind=Letter¦PrintScaleMode=1
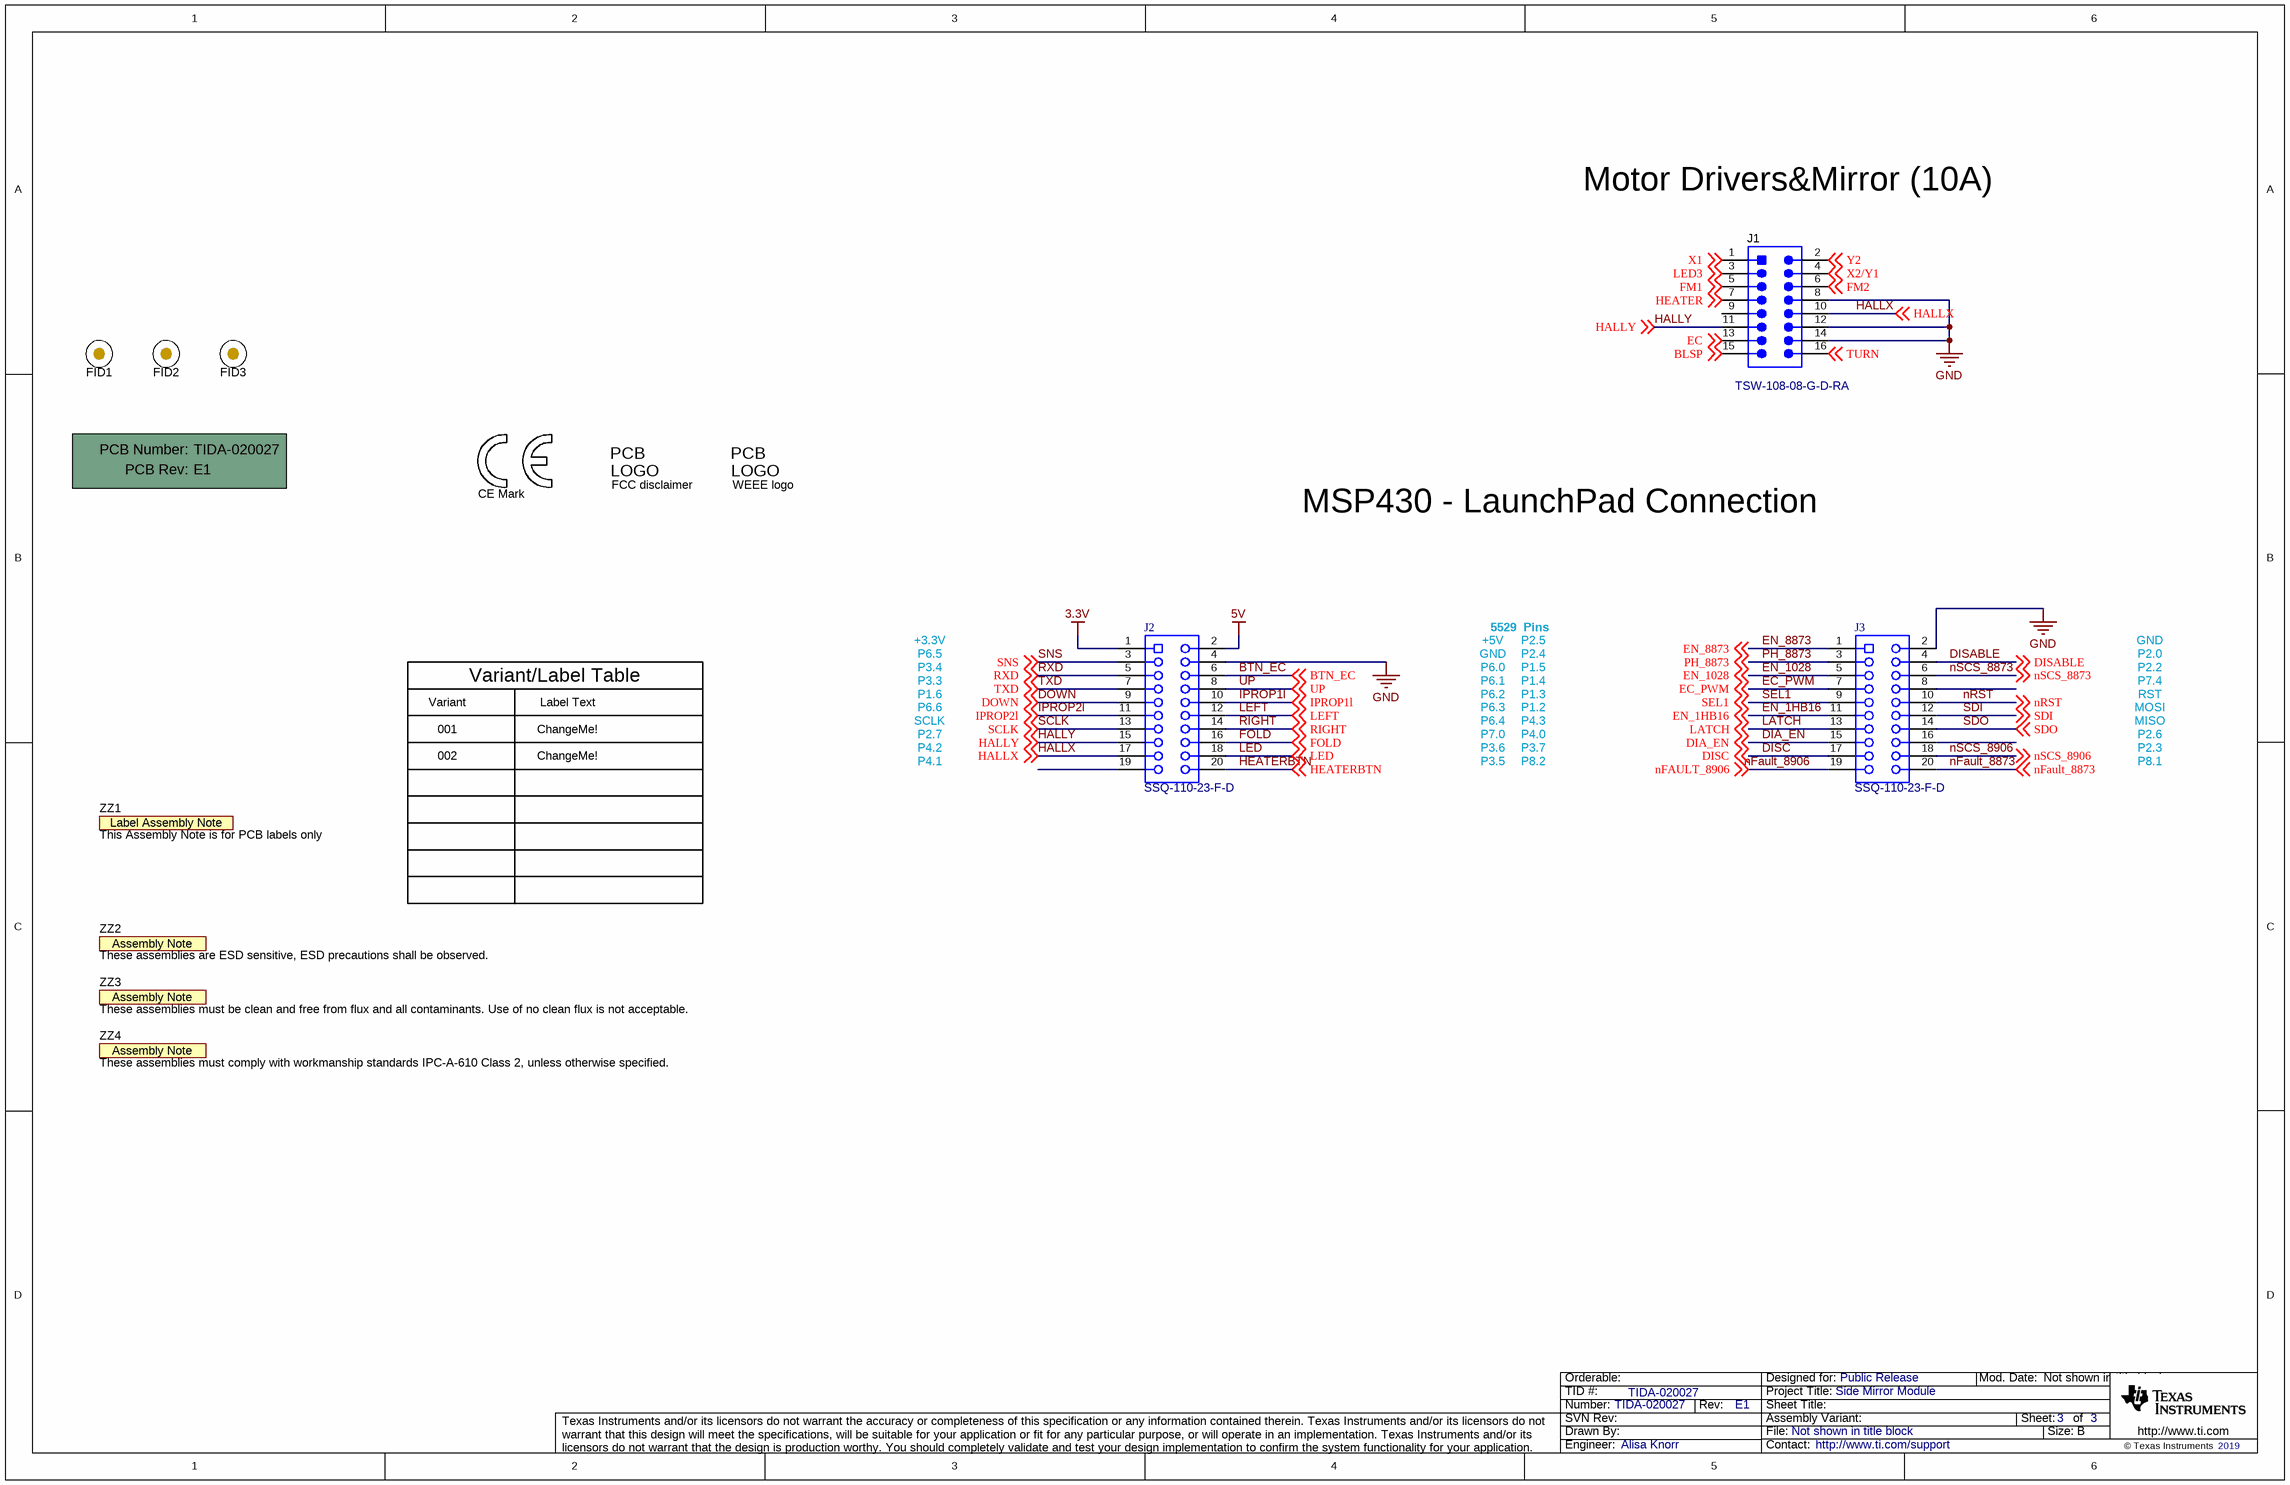
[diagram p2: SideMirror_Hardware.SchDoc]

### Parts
!PCB1  Printed Circuit Board  (value not drawn)  (mechanical)
FID1  Fiducial  [Fiducial10-20]  (value not drawn)
FID2  Fiducial  [Fiducial10-20]  (value not drawn)
FID3  Fiducial  [Fiducial10-20]  (value not drawn)
J1  TSW-108-08-G-D-RA  [GPSI16]
J2  SSQ-110-23-F-D  [Samtec_SSQ-110-23-F-D]
J3  SSQ-110-23-F-D  [Samtec_SSQ-110-23-F-D]
Logo1  CE Mark  [CE_Mark_5mm]  (no BOM)
Logo3  FCC disclaimer  [FCC_disclaimer]  (no BOM)
Logo4  WEEE logo  [WEEE_Minimum]  (no BOM)
ZZ1  This Assembly Note is for PCB labels only  [AssemblyNoteLabel]  (no BOM)
ZZ2  These assemblies are ESD sensitive, ESD precautions shall be observed.  [AssemblyNote]  (no BOM)
ZZ3  These assemblies must be clean and free from flux and all contaminants. Use of no clean flux is not acceptable.  [AssemblyNote]  (no BOM)
ZZ4  These assemblies must comply with workmanship standards IPC-A-610 Class 2, unless otherwise specified.  [AssemblyNote]  (no BOM)

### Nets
3.3V: J2.1
5V: J2.2
GND: J1.8 J1.12 J1.14 J2.4 J3.2
BLSP: J1.15 ; off-sheet BLSP
BTN_EC: J2.6 ; off-sheet BTN_EC
DIA_EN: J3.15 ; off-sheet DIA_EN
DISABLE: J3.4 ; off-sheet DISABLE
DISC: J3.17 ; off-sheet DISC
DOWN: J2.9 ; off-sheet DOWN
EC: J1.13 ; off-sheet EC
EC_PWM: J3.7 ; off-sheet EC_PWM
EN_1HB16: J3.11 ; off-sheet EN_1HB16
EN_1028: J3.5 ; off-sheet EN_1028
EN_8873: J3.1 ; off-sheet EN_8873
FM1: J1.5 ; off-sheet FM1
FM2: J1.6 ; off-sheet FM2
FOLD: J2.16 ; off-sheet FOLD
HALLX: J1.10 J2.17 ; off-sheet HALLX
HALLY: J1.11 J2.15 ; off-sheet HALLY
HEATER: J1.7 ; off-sheet HEATER
HEATERBTN: J2.20 ; off-sheet HEATERBTN
IPROP1l: J2.10 ; off-sheet IPROP1l
IPROP2l: J2.11 ; off-sheet IPROP2l
LATCH: J3.13 ; off-sheet LATCH
LED: J2.18 ; off-sheet LED
LED3: J1.3 ; off-sheet LED3
LEFT: J2.12 ; off-sheet LEFT
nFAULT_8873: J3.20 ; off-sheet nFault_8873
nFAULT_8906: J3.19 ; off-sheet nFAULT_8906
nRST: J3.10 ; off-sheet nRST
nSCS_8873: J3.6 ; off-sheet nSCS_8873
nSCS_8906: J3.18 ; off-sheet nSCS_8906
PH_8873: J3.3 ; off-sheet PH_8873
RIGHT: J2.14 ; off-sheet RIGHT
RXD: J2.5 ; off-sheet RXD
SCLK: J2.13 ; off-sheet SCLK
SDI: J3.12 ; off-sheet SDI
SDO: J3.14 ; off-sheet SDO
SEL1: J3.9 ; off-sheet SEL1
SNS: J2.3 ; off-sheet SNS
TURN: J1.16 ; off-sheet TURN
TXD: J2.7 ; off-sheet TXD
UP: J2.8 ; off-sheet UP
X1: J1.1 ; off-sheet X1
X2/Y1: J1.4 ; off-sheet X2/Y1
Y2: J1.2 ; off-sheet Y2

Not connected (* = marked no-connect by the designer): J1 9; J2 19; J3 8 16

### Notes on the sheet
- Motor Drivers&Mirror (10A)
- MSP430 - LaunchPad Connection
- 5529  Pins
- Variant
- Variant/Label Table
- Label Text
- +3.3V
- P6.5
- P3.4
- P3.3
- P1.6
- +5V
- GND
- P6.0
- P6.1
- P6.2
- P2.5
- P2.4
- P1.5
- P1.4
- P1.3
- P2.0
- P2.2
- P7.4
- RST
- 001
- 002
- ChangeMe!
- P6.6
- SCLK
- P2.7
- P4.2
- P4.1
- P6.3
- P6.4
- P7.0
- P3.6
- P3.5
- P1.2
- P4.3
- P4.0
- P3.7
- P8.2
- MOSI
- MISO
- P2.6
- P2.3
- P8.1
- Labels drawn without touching a wire or pin: nFault_8906

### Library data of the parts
!PCB1 = CMP-0003618-2: Manufacturer: Any; PartNumber: TIDA-020027
FID1-FID3 = CMP-0077181-1: Fiducial mark.  There is nothing to buy or mount.
J1 = CMP-0075420-1: Header, 100mil, 8x2, Gold, R/A, TH; Manufacturer: Samtec; Pitch_mm: 2.54; Cert_VDE: N; Gender: Male; Cert_CSA: Y; Voltage_V: 550V; Green_REACh: Passed; Current_A: 6.3A; CT: False; Green_Lifecycle: Active; Row_Count: 2; CNHeader: True
J2 J3 = CMP-0055675-1: Receptacle, 2.54mm, 10x2, Gold, TH; Manufacturer: Samtec; CNHeader: FALSE; Current_A: 6.3A; Gender: Female; Cert_CSA: Y; Voltage_V: 550V; CompType: Socket Strip; Row_Count: 2; RowSpacing_mm: 2.54; CT: TRUE
Logo1 = CMP-0074844-1: SymbolCreator: a0412235
Logo3 = CMP-0074847-1: FCC_disclaimer; Library Reference: Logo
Logo4 = CMP-0074769-1
ZZ1 = CMP-0003616-3
ZZ2 = CMP-0077236-1
ZZ3 = CMP-0077237-1
ZZ4 = CMP-0077238-1

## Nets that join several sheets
3.3V: SideMirror_Drivers (6 pins), SideMirror_Logic_TLIN1028 (8 pins), SideMirror_Hardware (J2.1)
GND: SideMirror_Drivers (16 pins), SideMirror_Logic_TLIN1028 (32 pins), SideMirror_Hardware (5 pins)
Vsup: SideMirror_Drivers (9 pins), SideMirror_Logic_TLIN1028 (10 pins)
BLSP: SideMirror_Drivers (R1.2), SideMirror_Hardware (J1.15)
DIA_EN: SideMirror_Logic_TLIN1028 (R13.1), SideMirror_Hardware (J3.15)
DISABLE: SideMirror_Drivers (U2.9), SideMirror_Hardware (J3.4)
DISC: SideMirror_Logic_TLIN1028 (Q3.1 R17.1), SideMirror_Hardware (J3.17)
EC: SideMirror_Logic_TLIN1028 (C22.1 Q3.3 Q4.3 R16.2), SideMirror_Hardware (J1.13)
EC_PWM: SideMirror_Logic_TLIN1028 (R21.1), SideMirror_Hardware (J3.7)
EN_1HB16: SideMirror_Logic_TLIN1028 (R10.1), SideMirror_Hardware (J3.11)
EN_1028: SideMirror_Logic_TLIN1028 (U4.2), SideMirror_Hardware (J3.5)
EN_8873: SideMirror_Drivers (U2.7), SideMirror_Hardware (J3.1)
FM1: SideMirror_Drivers (U2.18 U2.19), SideMirror_Hardware (J1.5)
FM2: SideMirror_Drivers (U2.14 U2.15), SideMirror_Hardware (J1.6)
HEATER: SideMirror_Logic_TLIN1028 (C16.1 U3.6 U3.7 U3.8), SideMirror_Hardware (J1.7)
IPROP1l: SideMirror_Drivers (R7.2 U2.10), SideMirror_Hardware (J2.10)
IPROP2l: SideMirror_Drivers (R6.2 U2.12), SideMirror_Hardware (J2.11)
LATCH: SideMirror_Logic_TLIN1028 (R11.1), SideMirror_Hardware (J3.13)
LED3: SideMirror_Drivers (R5.2), SideMirror_Hardware (J1.3)
nFAULT_8873: SideMirror_Drivers (R4.1 U2.2), SideMirror_Hardware (J3.20)
nFAULT_8906: SideMirror_Drivers (R2.1 U1.12), SideMirror_Hardware (J3.19)
nRST: SideMirror_Logic_TLIN1028 (U4.7), SideMirror_Hardware (J3.10)
nSCS_8873: SideMirror_Drivers (U2.6), SideMirror_Hardware (J3.6)
nSCS_8906: SideMirror_Drivers (U1.19), SideMirror_Hardware (J3.18)
PH_8873: SideMirror_Drivers (U2.8), SideMirror_Hardware (J3.3)
RXD: SideMirror_Logic_TLIN1028 (R19.1 U4.5), SideMirror_Hardware (J2.5)
SCLK: SideMirror_Drivers (U1.20 U2.5), SideMirror_Hardware (J2.13)
SDI: SideMirror_Drivers (U1.5 U2.4), SideMirror_Hardware (J3.12)
SDO: SideMirror_Drivers (U1.7 U2.3), SideMirror_Hardware (J3.14)
SEL1: SideMirror_Logic_TLIN1028 (R12.1), SideMirror_Hardware (J3.9)
SNS: SideMirror_Logic_TLIN1028 (C21.2 R15.1), SideMirror_Hardware (J2.3)
TURN: SideMirror_Drivers (R3.2), SideMirror_Hardware (J1.16)
TXD: SideMirror_Logic_TLIN1028 (R20.1), SideMirror_Hardware (J2.7)
VCP: SideMirror_Drivers (C8.2 U2.21), SideMirror_Logic_TLIN1028 (R9.2)
X1: SideMirror_Drivers (U1.3), SideMirror_Hardware (J1.1)
X2/Y1: SideMirror_Drivers (U1.10), SideMirror_Hardware (J1.4)
Y2: SideMirror_Drivers (U1.2), SideMirror_Hardware (J1.2)

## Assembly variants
001: not fitted D3 FID1 FID2 FID3 R16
